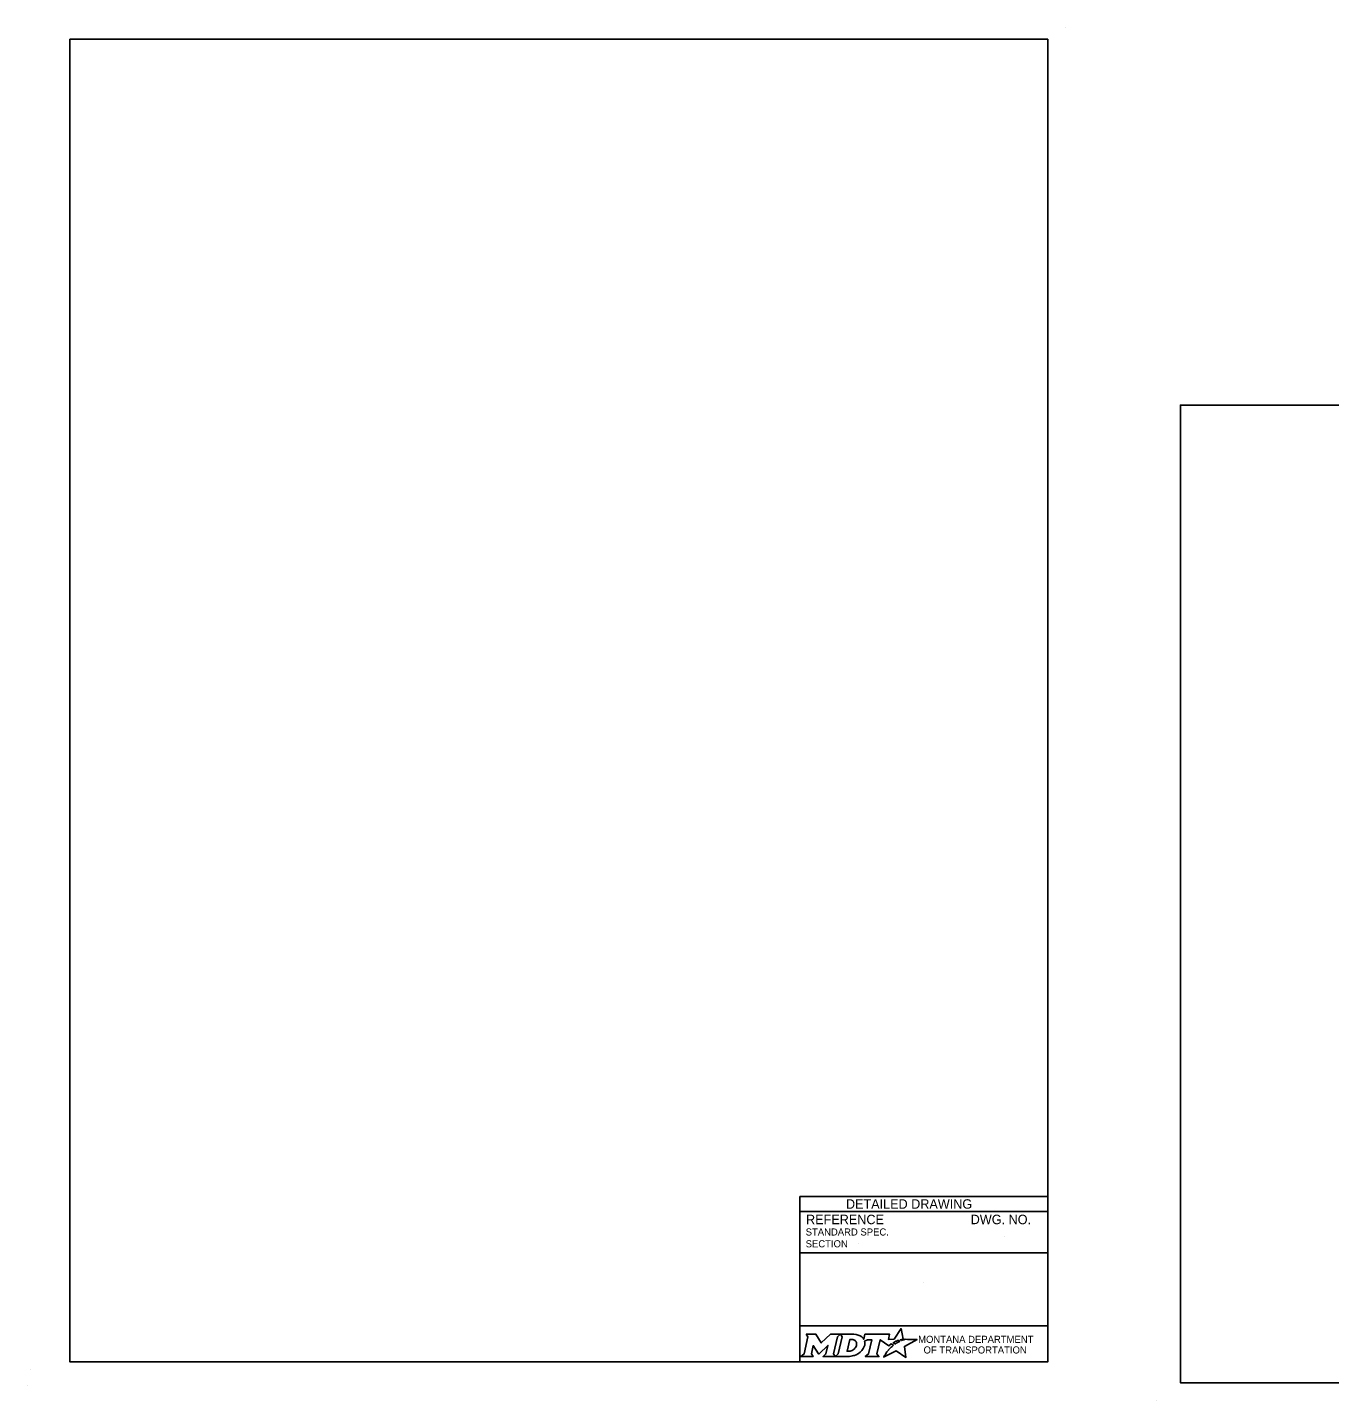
# Model space of a CAD drawing. Extents: x 49991 to 50160, y 49948 to 50051.
# Drawn here: x 49999.98 to 50011, y 49999.74 to 50011.36 of the extents above; entities that cross this region are included whole.
import ezdxf

# ---------------------------------------------------------------- set-up
doc = ezdxf.new("R2010")
doc.units = 0
doc.layers.add('Level 1', color=7, linetype='Continuous')
doc.layers.add('Level 2', color=7, linetype='Continuous')

msp = doc.modelspace()

# ---------------------------------------------------------------- linework, layer by layer
at = {"layer": 'Level 1'}
for p, q in [((50008.765, 50011.363), (50008.765, 50011.363)), ((49999.977, 49999.862), (49999.977, 49999.862)), ((50009.537, 49999.736), (50009.537, 49999.736))]:
    msp.add_line(p, q, dxfattribs=at)
for points in [[(50008.615, 50011.263), (50000.336, 50011.263), (50000.336, 50000.062), (50008.615, 50000.062)], [(50020.938, 50008.165), (50009.737, 50008.165), (50009.737, 49999.886), (50020.938, 49999.886)]]:
    msp.add_lwpolyline(points, close=True, dxfattribs=at)
at = {"layer": 'Level 2'}
for p, q in [((50008.615, 50001.462), (50006.515, 50001.462)), ((50006.515, 50001.462), (50006.515, 50000.062)), ((50008.615, 50001.337), (50006.515, 50001.337)), ((50007.009, 50001.063), (50007.009, 50001.063)), ((50008.251, 50001.122), (50008.251, 50001.122)), ((50008.615, 50000.987), (50006.515, 50000.987)), ((50007.565, 50000.738), (50007.565, 50000.738)), ((50008.615, 50000.369), (50006.515, 50000.369)), ((50000, 50000), (50000, 50000))]:
    msp.add_line(p, q, dxfattribs=at)
for points in [[(50007.377, 50000.245), (50007.367, 50000.25), (50007.378, 50000.253), (50007.39, 50000.255), (50007.373, 50000.345), (50007.313, 50000.254), (50007.266, 50000.253), (50007.276, 50000.297), (50007.067, 50000.297), (50007.057, 50000.255), (50007.051, 50000.263)], [(50006.57, 50000.297), (50006.584, 50000.274), (50006.551, 50000.131), (50006.525, 50000.108), (50006.627, 50000.108), (50006.613, 50000.131), (50006.629, 50000.201), (50006.673, 50000.132), (50006.678, 50000.132), (50006.753, 50000.202), (50006.737, 50000.13), (50006.712, 50000.108), (50006.814, 50000.108), (50006.8, 50000.132), (50006.833, 50000.274)], [(50006.833, 50000.274), (50006.859, 50000.297), (50006.776, 50000.297), (50006.697, 50000.224), (50006.652, 50000.297), (50006.57, 50000.297)], [(50006.972, 50000.297), (50006.859, 50000.297), (50006.873, 50000.275), (50006.839, 50000.131), (50006.814, 50000.108), (50006.925, 50000.108)], [(50006.996, 50000.211), (50006.995, 50000.203), (50006.992, 50000.193), (50006.988, 50000.185), (50006.982, 50000.178), (50006.976, 50000.171), (50006.968, 50000.164), (50006.959, 50000.16), (50006.95, 50000.156), (50006.941, 50000.154), (50006.932, 50000.153), (50006.916, 50000.153), (50006.94, 50000.253), (50006.956, 50000.253), (50006.963, 50000.252), (50006.971, 50000.25), (50006.977, 50000.247), (50006.983, 50000.243), (50006.988, 50000.238), (50006.992, 50000.232), (50006.995, 50000.226), (50006.996, 50000.218), (50006.996, 50000.215), (50006.996, 50000.211)], [(50007.064, 50000.238), (50007.088, 50000.251), (50007.125, 50000.251), (50007.097, 50000.131), (50007.069, 50000.108), (50007.185, 50000.108), (50007.168, 50000.131), (50007.196, 50000.251), (50007.268, 50000.2), (50007.289, 50000.215), (50007.309, 50000.204)], [(50007.253, 50000.148), (50007.237, 50000.124), (50007.233, 50000.116), (50007.227, 50000.107), (50007.225, 50000.103), (50007.33, 50000.156), (50007.414, 50000.101), (50007.401, 50000.194), (50007.508, 50000.252), (50007.458, 50000.253), (50007.428, 50000.253), (50007.407, 50000.254), (50007.401, 50000.252), (50007.396, 50000.251), (50007.387, 50000.249), (50007.377, 50000.245)], [(50007.327, 50000.217), (50007.324, 50000.215), (50007.306, 50000.225), (50007.316, 50000.231), (50007.32, 50000.233), (50007.329, 50000.237), (50007.335, 50000.239), (50007.343, 50000.243), (50007.35, 50000.245), (50007.362, 50000.238), (50007.358, 50000.236), (50007.353, 50000.233), (50007.349, 50000.231), (50007.344, 50000.228), (50007.342, 50000.227), (50007.339, 50000.225), (50007.337, 50000.224), (50007.334, 50000.222), (50007.332, 50000.221), (50007.329, 50000.219), (50007.327, 50000.217)], [(50006.97, 50000.116), (50006.979, 50000.118), (50006.992, 50000.124), (50007.012, 50000.135)], [(50007.267, 50000.164), (50007.267, 50000.164)]]:
    msp.add_lwpolyline(points, dxfattribs=at)
for centre, radius, start, end in [((50006.995, 50000.219), 0.0709, 339.5329, 15.8582), ((50006.951, 50000.236), 0.118, 300.9103, 339.1383)]:
    msp.add_arc(centre, radius, start, end, dxfattribs=at)
for centre, major_axis, ratio, start_param, end_param in [((50006.97, 50000.25), (0.0834, -0.0037), 0.568097, 0.61298, 1.570796), ((50007.026, 50000.257), (0.0361, -0.0295), 0.469099, 1.225588, 1.570796), ((50006.925, 50000.257), (0, 0.148), 0.987302, 3.139398, 3.456847), ((50007.26, 50000.156), (-0.00694, -0.00806), 0.008222, 0, 3.137361), ((50007.276, 50000.174), (-0.0098, -0.0102), 0.016458, 3.141593, 6.279097), ((50007.297, 50000.194), (-0.0112, -0.0097), 0.021651, 3.157348, 6.283185)]:
    msp.add_ellipse(centre, major_axis=major_axis, ratio=ratio, start_param=start_param, end_param=end_param, dxfattribs=at)

# ---------------------------------------------------------------- texts
for s, height, p in [('DETAILED DRAWING', 0.0799, (50006.906, 50001.36)), ('REFERENCE', 0.08, (50006.568, 50001.229)), ('DWG. NO.', 0.08, (50007.962, 50001.229)), ('STANDARD SPEC.', 0.06, (50006.565, 50001.133)), ('SECTION', 0.06, (50006.565, 50001.033))]:
    msp.add_text(s, height=height, dxfattribs=at).set_placement(p)
for s, p in [('MONTANA DEPARTMENT', (50007.517, 50000.224)), ('OF TRANSPORTATION', (50007.563, 50000.134))]:
    msp.add_text(s, height=0.06, rotation=360, dxfattribs=at).set_placement(p)

doc.saveas('drawing.dxf')
